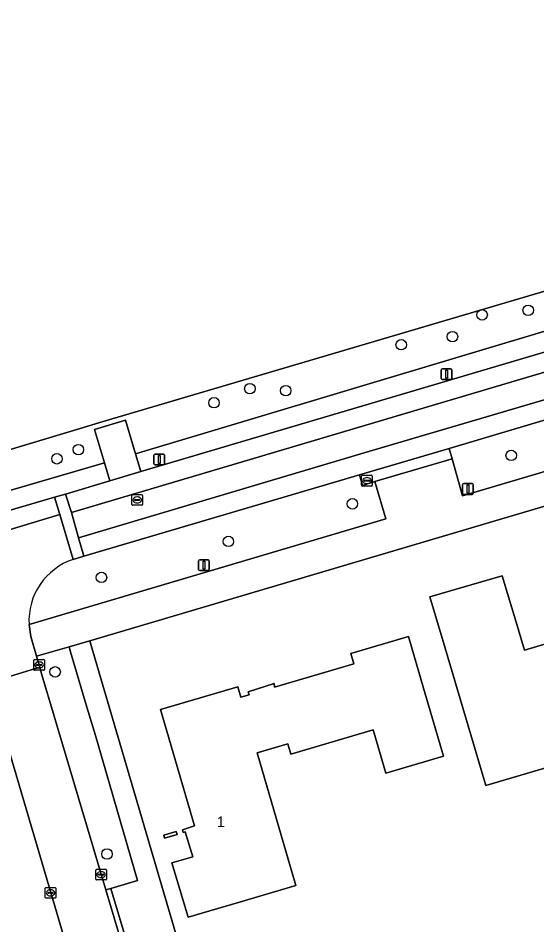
# Model space of a CAD drawing. Extents: x 162417 to 163722, y 384268 to 385417.
# Drawn here: x 163303.2 to 163351.6, y 384656 to 384740.4 of the extents above; entities that cross this region are included whole.
import ezdxf

# ---------------------------------------------------------------- set-up
doc = ezdxf.new("R2010")
doc.units = 0
for name, color, linetype in [('IMGEO_Berm_groen', 7, 'Continuous'), ('IMGEO_Boom', 7, 'Continuous'), ('IMGEO_Erf', 7, 'Continuous'), ('IMGEO_Groenvoorziening', 7, 'Continuous'), ('IMGEO_Hek', 7, 'Continuous'), ('IMGEO_Kolk', 7, 'Continuous'), ('IMGEO_Lichtmast', 7, 'Continuous'), ('IMGEO_Pand', 7, 'Continuous'), ('IMGEO_Pand_nummerreeks', 7, 'Continuous'), ('IMGEO_Rijbaan_lokaal_gesloten', 7, 'Continuous'), ('IMGEO_Rijbaan_lokaal_open', 7, 'Continuous'), ('IMGEO_Rioolput', 7, 'Continuous'), ('IMGEO_Voetpad_open', 7, 'Continuous')]:
    doc.layers.add(name, color=color, linetype=linetype)

msp = doc.modelspace()

# ---------------------------------------------------------------- linework, layer by layer
at = {"layer": 'IMGEO_Berm_groen'}
msp.add_lwpolyline([(163310.423, 384673.599), (163309.634, 384676.252), (163308.098, 384681.397), (163307.99, 384681.867), (163304.927, 384681.002), (163305.248, 384679.964), (163305.445, 384679.26), (163306.588, 384675.415), (163311.404, 384659.211), (163311.865, 384659.348), (163314.36, 384660.087)], close=True, dxfattribs=at)
at = {"layer": 'IMGEO_Boom'}
for centre in [(163350.764, 384713.205), (163346.474, 384712.775), (163343.706, 384710.75), (163338.932, 384709.998), (163324.825, 384705.903), (163328.166, 384705.722), (163321.48, 384704.594), (163308.84, 384700.227), (163349.182, 384699.69), (163306.838, 384699.373), (163334.381, 384695.178), (163322.822, 384691.68), (163310.99, 384688.327), (163306.669, 384679.527), (163311.506, 384662.56)]:
    msp.add_circle(centre, 0.489, dxfattribs=at)
at = {"layer": 'IMGEO_Erf'}
for points in [[(163175.984, 384894.871), (163189.317, 384805.604), (163189.37, 384805.252), (163225.47, 384820.661), (163226.246, 384820.995), (163226.612, 384820.203), (163229.945, 384812.987), (163225.751, 384811.048), (163227.566, 384807.013), (163229.658, 384807.895), (163230.655, 384805.678), (163228.563, 384804.796), (163224.144, 384802.92), (163192.437, 384789.411), (163200.664, 384750), (163215.633, 384678.291), (163252.312, 384685.775), (163256.147, 384686.557), (163258.646, 384687.067), (163309.002, 384702.202), (163311.14, 384702.845), (163432.284, 384738.586)], [(163439.207, 384659.583), (163443.713, 384668.387), (163445.245, 384671.173), (163447.549, 384675.363), (163448.047, 384676.269), (163448.203, 384676.553), (163447.906, 384676.713), (163460.651, 384701.67), (163461.429, 384701.275), (163462.377, 384703.14), (163461.604, 384703.558), (163465.046, 384710.362), (163457.241, 384724.223), (163456.356, 384725.796), (163426.302, 384716.894), (163404.174, 384710.339), (163359.949, 384697.239), (163309.903, 384682.414), (163310.09, 384681.76), (163333.508, 384602.071)], [(163310.764, 384635.802), (163312.926, 384636.415), (163300.634, 384677.935), (163300.352, 384678.47), (163299.946, 384679.602), (163217.164, 384655.09), (163211.589, 384653.439), (163162.154, 384638.801), (163163.733, 384633.465), (163163.883, 384632.961), (163162.442, 384632.589), (163160.726, 384632.111), (163162.281, 384626.769), (163162.11, 384626.271), (163182.33, 384558.292), (163182.739, 384554.615), (163182.929, 384552.906)]]:
    msp.add_lwpolyline(points, dxfattribs=at)
for points in [[(163363.589, 384671.02), (163357.808, 384669.308), (163356.639, 384673.259), (163353.178, 384672.234), (163353.565, 384670.93), (163346.815, 384668.931), (163343.025, 384681.732), (163341.605, 384686.526), (163348.348, 384688.485), (163349.733, 384683.848), (163350.422, 384681.542), (163353.862, 384682.572), (163353.177, 384684.891), (163353.045, 384685.336), (163358.845, 384687.038), (163360.265, 384682.244)], [(163341.017, 384678.019), (163342.88, 384671.666), (163337.507, 384670.091), (163336.326, 384674.122), (163328.65, 384671.872), (163328.369, 384672.832), (163325.491, 384671.988), (163329.116, 384659.629), (163323.865, 384658.089), (163319.067, 384656.682), (163317.564, 384661.73), (163319.491, 384662.304), (163318.804, 384664.614), (163318.613, 384664.557), (163318.553, 384664.813), (163319.674, 384665.19), (163316.483, 384676.015), (163323.701, 384678.122), (163323.982, 384677.163), (163324.76, 384677.39), (163324.676, 384677.678), (163327.076, 384678.428), (163327.112, 384678.101), (163334.498, 384680.283), (163334.242, 384681.242), (163339.61, 384682.816)], [(163316.881, 384664.023), (163316.81, 384664.316), (163317.961, 384664.654), (163318.048, 384664.37)]]:
    msp.add_lwpolyline(points, close=True, dxfattribs=at)
at = {"layer": 'IMGEO_Groenvoorziening'}
for points in [[(163434.845, 384735.97), (163434.107, 384738.766), (163432.394, 384738.238), (163432.284, 384738.586), (163311.14, 384702.845), (163309.002, 384702.202), (163258.646, 384687.067), (163256.147, 384686.557), (163256.857, 384683.119), (163311.275, 384698.988), (163310.335, 384702.113), (163313.232, 384702.984), (163314.169, 384699.824)], [(163378.093, 384716.936), (163379.085, 384717.235), (163384.338, 384718.783), (163385.387, 384719.108), (163412.606, 384727.101), (163435.394, 384733.889), (163434.845, 384735.97), (163314.169, 384699.824), (163314.653, 384698.19)], [(163375.527, 384705.045), (163374.472, 384708.486), (163373.407, 384708.185), (163373.123, 384709.18), (163343.412, 384700.333), (163343.683, 384699.355), (163344.653, 384695.917)], [(163289.436, 384690.763), (163290.424, 384691.053), (163306.618, 384695.814), (163307.647, 384696.083), (163311.775, 384697.325), (163311.275, 384698.988), (163256.857, 384683.119), (163257.233, 384681.296)]]:
    msp.add_lwpolyline(points, close=True, dxfattribs=at)
for points in [[(163337.499, 384693.791), (163336.478, 384697.246), (163335.325, 384696.897), (163335.047, 384697.894), (163309.345, 384690.294), (163308.357, 384690.004)], [(163304.239, 384683.939), (163337.499, 384693.791)]]:
    msp.add_lwpolyline(points, dxfattribs=at)
msp.add_arc((163310.267, 384684.277), 6.037, 108.44151, 183.20723, dxfattribs=at)
at = {"layer": 'IMGEO_Hek'}
msp.add_lwpolyline([(163309.002, 384702.202), (163311.14, 384702.845)], dxfattribs=at)
at = {"layer": 'IMGEO_Kolk'}
for p, q in [((163335.233, 384696.91), (163335.233, 384697.762)), ((163335.308, 384697.836), (163336.16, 384697.836)), ((163336.234, 384697.762), (163336.234, 384696.91)), ((163336.16, 384696.836), (163335.308, 384696.836)), ((163335.492, 384697.33), (163335.492, 384697.342)), ((163335.93, 384697.293), (163335.532, 384697.293)), ((163335.535, 384697.379), (163335.933, 384697.379)), ((163335.744, 384697.056), (163335.719, 384697.056)), ((163335.721, 384697.616), (163335.746, 384697.616)), ((163335.976, 384697.342), (163335.976, 384697.33)), ((163304.675, 384679.749), (163304.675, 384680.601)), ((163304.75, 384680.675), (163305.602, 384680.675)), ((163304.934, 384680.169), (163304.934, 384680.181)), ((163305.372, 384680.132), (163304.974, 384680.132)), ((163304.977, 384680.218), (163305.375, 384680.218)), ((163305.163, 384680.455), (163305.188, 384680.455)), ((163305.418, 384680.181), (163305.418, 384680.169)), ((163305.676, 384680.601), (163305.676, 384679.749)), ((163305.602, 384679.675), (163304.75, 384679.675)), ((163305.186, 384679.895), (163305.161, 384679.895)), ((163310.459, 384660.215), (163310.459, 384661.067)), ((163310.534, 384661.141), (163311.386, 384661.141)), ((163310.718, 384660.635), (163310.718, 384660.647)), ((163311.156, 384660.598), (163310.758, 384660.598)), ((163310.761, 384660.684), (163311.159, 384660.684)), ((163310.947, 384660.921), (163310.972, 384660.921)), ((163311.202, 384660.647), (163311.202, 384660.635)), ((163311.46, 384661.067), (163311.46, 384660.215)), ((163311.386, 384660.141), (163310.534, 384660.141)), ((163310.97, 384660.361), (163310.945, 384660.361)), ((163305.74, 384658.517), (163305.74, 384659.369)), ((163305.815, 384659.443), (163306.667, 384659.443)), ((163305.999, 384658.937), (163305.999, 384658.949)), ((163306.437, 384658.9), (163306.039, 384658.9)), ((163306.042, 384658.986), (163306.44, 384658.986)), ((163306.228, 384659.223), (163306.253, 384659.223)), ((163306.483, 384658.949), (163306.483, 384658.937)), ((163306.741, 384659.369), (163306.741, 384658.517)), ((163306.667, 384658.443), (163305.815, 384658.443)), ((163306.251, 384658.663), (163306.226, 384658.663))]:
    msp.add_line(p, q, dxfattribs=at)
for points in [[(163335.233, 384696.91), (163335.233, 384697.762)], [(163335.308, 384697.836), (163336.16, 384697.836)], [(163336.234, 384697.762), (163336.234, 384696.91)], [(163336.16, 384696.836), (163335.308, 384696.836)], [(163304.675, 384679.749), (163304.675, 384680.601)], [(163304.75, 384680.675), (163305.602, 384680.675)], [(163305.676, 384680.601), (163305.676, 384679.749)], [(163305.602, 384679.675), (163304.75, 384679.675)], [(163310.459, 384660.215), (163310.459, 384661.067)], [(163310.534, 384661.141), (163311.386, 384661.141)], [(163311.46, 384661.067), (163311.46, 384660.215)], [(163311.386, 384660.141), (163310.534, 384660.141)], [(163305.74, 384658.517), (163305.74, 384659.369)], [(163305.815, 384659.443), (163306.667, 384659.443)], [(163306.741, 384659.369), (163306.741, 384658.517)], [(163306.667, 384658.443), (163305.815, 384658.443)]]:
    msp.add_lwpolyline(points, dxfattribs=at)
for centre, radius, start, end in [((163335.31, 384697.76), 0.0765, 91.55205, 178.44795), ((163335.31, 384697.76), 0.0765, 91.55205, 178.44795), ((163336.158, 384697.76), 0.0765, 1.55205, 88.44795), ((163336.158, 384697.76), 0.0765, 1.55205, 88.44795), ((163335.31, 384696.912), 0.0765, 181.55205, 268.44795), ((163335.31, 384696.912), 0.0765, 181.55205, 268.44795), ((163335.532, 384697.339), 0.0403, 85.87752, 175.75265), ((163335.529, 384697.329), 0.0366, 178.93798, 274.71019), ((163335.933, 384697.336), 0.043, 264.86636, 352.45326), ((163335.937, 384697.341), 0.0386, 1.73085, 96.63898), ((163336.158, 384696.912), 0.0765, 271.55205, 358.44795), ((163336.158, 384696.912), 0.0765, 271.55205, 358.44795), ((163304.752, 384680.599), 0.0765, 91.55205, 178.44795), ((163304.752, 384680.599), 0.0765, 91.55205, 178.44795), ((163304.974, 384680.178), 0.0403, 85.87752, 175.75265), ((163304.971, 384680.168), 0.0366, 178.93798, 274.71019), ((163305.375, 384680.175), 0.043, 264.86636, 352.45326), ((163305.379, 384680.18), 0.0386, 1.73085, 96.63898), ((163305.6, 384680.599), 0.0765, 1.55205, 88.44795), ((163305.6, 384680.599), 0.0765, 1.55205, 88.44795), ((163304.752, 384679.751), 0.0765, 181.55205, 268.44795), ((163304.752, 384679.751), 0.0765, 181.55205, 268.44795), ((163305.6, 384679.751), 0.0765, 271.55205, 358.44795), ((163305.6, 384679.751), 0.0765, 271.55205, 358.44795), ((163310.536, 384661.065), 0.0765, 91.55205, 178.44795), ((163310.536, 384661.065), 0.0765, 91.55205, 178.44795), ((163310.758, 384660.644), 0.0403, 85.87752, 175.75265), ((163310.755, 384660.634), 0.0366, 178.93798, 274.71019), ((163311.159, 384660.641), 0.043, 264.86636, 352.45326), ((163311.163, 384660.646), 0.0386, 1.73085, 96.63898), ((163311.384, 384661.065), 0.0765, 1.55205, 88.44795), ((163311.384, 384661.065), 0.0765, 1.55205, 88.44795), ((163310.536, 384660.217), 0.0765, 181.55205, 268.44795), ((163310.536, 384660.217), 0.0765, 181.55205, 268.44795), ((163311.384, 384660.217), 0.0765, 271.55205, 358.44795), ((163311.384, 384660.217), 0.0765, 271.55205, 358.44795), ((163305.817, 384659.367), 0.0765, 91.55205, 178.44795), ((163305.817, 384659.367), 0.0765, 91.55205, 178.44795), ((163306.039, 384658.946), 0.0403, 85.87752, 175.75265), ((163306.036, 384658.936), 0.0366, 178.93798, 274.71019), ((163306.44, 384658.943), 0.043, 264.86636, 352.45326), ((163306.444, 384658.948), 0.0386, 1.73085, 96.63898), ((163306.665, 384659.367), 0.0765, 1.55205, 88.44795), ((163306.665, 384659.367), 0.0765, 1.55205, 88.44795), ((163305.817, 384658.519), 0.0765, 181.55205, 268.44795), ((163305.817, 384658.519), 0.0765, 181.55205, 268.44795), ((163306.665, 384658.519), 0.0765, 271.55205, 358.44795), ((163306.665, 384658.519), 0.0765, 271.55205, 358.44795)]:
    msp.add_arc(centre, radius, start, end, dxfattribs=at)
for centre, major_axis, ratio, start_param, end_param in [((163335.72, 384697.336), (-0.387, 0.002), 0.722429, 4.712389, 7.853982), ((163335.745, 384697.336), (-0.39, 0.002), 0.717154, 1.570796, 4.712389), ((163305.162, 384680.175), (-0.387, 0.002), 0.722429, 4.712389, 7.853982), ((163305.187, 384680.175), (-0.39, 0.002), 0.717154, 1.570796, 4.712389), ((163310.946, 384660.641), (-0.387, 0.002), 0.722429, 4.712389, 7.853982), ((163310.971, 384660.641), (-0.39, 0.002), 0.717154, 1.570796, 4.712389), ((163306.227, 384658.943), (-0.387, 0.002), 0.722429, 4.712389, 7.853982), ((163306.252, 384658.943), (-0.39, 0.002), 0.717154, 1.570796, 4.712389)]:
    msp.add_ellipse(centre, major_axis=major_axis, ratio=ratio, start_param=start_param, end_param=end_param, dxfattribs=at)
at = {"layer": 'IMGEO_Lichtmast'}
for p, q in [((163342.664, 384706.864), (163342.664, 384707.664)), ((163342.664, 384707.664), (163342.664, 384706.864)), ((163342.764, 384707.764), (163343.554, 384707.764)), ((163343.554, 384707.764), (163342.764, 384707.764)), ((163343.654, 384707.664), (163343.654, 384706.864)), ((163343.654, 384706.864), (163343.654, 384707.664)), ((163343.554, 384706.764), (163342.764, 384706.764)), ((163342.764, 384706.764), (163343.554, 384706.764)), ((163315.882, 384698.906), (163315.882, 384699.706)), ((163315.882, 384699.706), (163315.882, 384698.906)), ((163315.982, 384699.806), (163316.772, 384699.806)), ((163316.772, 384699.806), (163315.982, 384699.806)), ((163316.872, 384699.706), (163316.872, 384698.906)), ((163316.872, 384698.906), (163316.872, 384699.706)), ((163316.772, 384698.806), (163315.982, 384698.806)), ((163315.982, 384698.806), (163316.772, 384698.806)), ((163344.657, 384696.161), (163344.657, 384696.961)), ((163344.657, 384696.961), (163344.657, 384696.161)), ((163344.757, 384697.061), (163345.547, 384697.061)), ((163345.547, 384697.061), (163344.757, 384697.061)), ((163345.647, 384696.961), (163345.647, 384696.161)), ((163345.647, 384696.161), (163345.647, 384696.961)), ((163345.547, 384696.061), (163344.757, 384696.061)), ((163344.757, 384696.061), (163345.547, 384696.061)), ((163320.047, 384689.071), (163320.047, 384689.871)), ((163320.047, 384689.871), (163320.047, 384689.071)), ((163320.147, 384689.971), (163320.937, 384689.971)), ((163320.937, 384689.971), (163320.147, 384689.971)), ((163321.037, 384689.871), (163321.037, 384689.071)), ((163321.037, 384689.071), (163321.037, 384689.871)), ((163320.937, 384688.971), (163320.147, 384688.971)), ((163320.147, 384688.971), (163320.937, 384688.971))]:
    msp.add_line(p, q, dxfattribs=at)
for points in [[(163343.084, 384707.639), (163343.234, 384707.639), (163343.234, 384706.889), (163343.084, 384706.889), (163343.084, 384707.639)], [(163316.302, 384699.681), (163316.452, 384699.681), (163316.452, 384698.931), (163316.302, 384698.931), (163316.302, 384699.681)], [(163345.077, 384696.936), (163345.227, 384696.936), (163345.227, 384696.186), (163345.077, 384696.186), (163345.077, 384696.936)], [(163320.467, 384689.846), (163320.617, 384689.846), (163320.617, 384689.096), (163320.467, 384689.096), (163320.467, 384689.846)]]:
    msp.add_lwpolyline(points, dxfattribs=at)
for centre, start, end in [((163342.764, 384707.664), 90, 180), ((163342.764, 384707.664), 90, 180), ((163343.554, 384707.664), 0, 90), ((163343.554, 384707.664), 360, 90), ((163342.764, 384706.864), 180, 270), ((163342.764, 384706.864), 180, 270), ((163343.554, 384706.864), 270, 0), ((163343.554, 384706.864), 270, 0), ((163315.982, 384699.706), 90, 180), ((163315.982, 384699.706), 90, 180), ((163316.772, 384699.706), 0, 90), ((163316.772, 384699.706), 360, 90), ((163315.982, 384698.906), 180, 270), ((163315.982, 384698.906), 180, 270), ((163316.772, 384698.906), 270, 0), ((163316.772, 384698.906), 270, 0), ((163344.757, 384696.961), 90, 180), ((163344.757, 384696.961), 90, 180), ((163345.547, 384696.961), 0, 90), ((163345.547, 384696.961), 360, 90), ((163344.757, 384696.161), 180, 270), ((163344.757, 384696.161), 180, 270), ((163345.547, 384696.161), 270, 0), ((163345.547, 384696.161), 270, 0), ((163320.147, 384689.871), 90, 180), ((163320.147, 384689.871), 90, 180), ((163320.937, 384689.871), 0, 90), ((163320.937, 384689.871), 360, 90), ((163320.147, 384689.071), 180, 270), ((163320.147, 384689.071), 180, 270), ((163320.937, 384689.071), 270, 0), ((163320.937, 384689.071), 270, 0)]:
    msp.add_arc(centre, 0.1, start, end, dxfattribs=at)
at = {"layer": 'IMGEO_Pand'}
for points in [[(163346.815, 384668.931), (163353.565, 384670.93), (163353.178, 384672.234), (163356.639, 384673.259), (163357.808, 384669.308), (163363.589, 384671.02), (163360.265, 384682.244), (163358.845, 384687.038), (163353.045, 384685.336), (163353.177, 384684.891), (163353.862, 384682.572), (163350.422, 384681.542), (163349.733, 384683.848), (163348.348, 384688.485), (163341.605, 384686.526), (163343.025, 384681.732)], [(163339.61, 384682.816), (163334.242, 384681.242), (163334.498, 384680.283), (163327.112, 384678.101), (163327.076, 384678.428), (163324.676, 384677.678), (163324.76, 384677.39), (163323.982, 384677.163), (163323.701, 384678.122), (163316.483, 384676.015), (163319.674, 384665.19), (163318.553, 384664.813), (163318.613, 384664.557), (163318.804, 384664.614), (163319.491, 384662.304), (163317.564, 384661.73), (163319.067, 384656.682), (163323.865, 384658.089), (163329.116, 384659.629), (163325.491, 384671.988), (163328.369, 384672.832), (163328.65, 384671.872), (163336.326, 384674.122), (163337.507, 384670.091), (163342.88, 384671.666), (163341.017, 384678.019)], [(163316.81, 384664.316), (163316.881, 384664.023), (163318.048, 384664.37), (163317.961, 384664.654)]]:
    msp.add_lwpolyline(points, close=True, dxfattribs=at)
at = {"layer": 'IMGEO_Rijbaan_lokaal_gesloten'}
for points in [[(163314.653, 384698.19), (163311.775, 384697.325), (163307.647, 384696.083), (163308.184, 384694.376), (163378.569, 384715.229), (163378.093, 384716.936)], [(163379.769, 384711.14), (163379.278, 384712.828), (163335.473, 384699.928), (163308.845, 384692.001), (163309.345, 384690.294), (163335.047, 384697.894), (163343.412, 384700.333), (163373.123, 384709.18), (163377.923, 384710.618)], [(163290.424, 384691.053), (163290.945, 384689.301), (163307.122, 384694.182), (163306.618, 384695.814)]]:
    msp.add_lwpolyline(points, close=True, dxfattribs=at)
at = {"layer": 'IMGEO_Rijbaan_lokaal_open'}
for points in [[(163379.278, 384712.828), (163378.569, 384715.229), (163308.184, 384694.376), (163308.845, 384692.001), (163335.473, 384699.928)], [(163308.357, 384690.004), (163309.345, 384690.294), (163308.845, 384692.001), (163308.184, 384694.376), (163307.647, 384696.083), (163306.618, 384695.814), (163307.122, 384694.182)]]:
    msp.add_lwpolyline(points, close=True, dxfattribs=at)
for points in [[(163308.357, 384690.004), (163307.122, 384694.182), (163290.945, 384689.301), (163292.104, 384685.298)], [(163298.709, 384682.365), (163299.946, 384679.602), (163300.352, 384678.47), (163305.248, 384679.964), (163304.927, 384681.002), (163304.395, 384682.827), (163304.239, 384683.939)], [(163322.986, 384620.355), (163322.7, 384621.313), (163321.795, 384624.338), (163321.537, 384625.199), (163317.662, 384638.152), (163313.725, 384651.399), (163311.404, 384659.211), (163306.588, 384675.415), (163305.445, 384679.26), (163305.248, 384679.964), (163300.352, 384678.47), (163300.634, 384677.935), (163312.926, 384636.415), (163317.237, 384621.888), (163323.475, 384600.863), (163323.936, 384598.792), (163323.763, 384596.699)]]:
    msp.add_lwpolyline(points, dxfattribs=at)
msp.add_arc((163310.267, 384684.277), 6.037, 108.44151, 183.20723, dxfattribs=at)
at = {"layer": 'IMGEO_Rioolput'}
for p, q in [((163313.82, 384695.117), (163313.82, 384695.969)), ((163313.895, 384696.043), (163314.747, 384696.043)), ((163314.821, 384695.969), (163314.821, 384695.117)), ((163314.079, 384695.537), (163314.079, 384695.549)), ((163314.517, 384695.5), (163314.119, 384695.5)), ((163314.122, 384695.586), (163314.52, 384695.586)), ((163314.331, 384695.263), (163314.306, 384695.263)), ((163314.308, 384695.823), (163314.333, 384695.823)), ((163314.563, 384695.549), (163314.563, 384695.537)), ((163314.747, 384695.043), (163313.895, 384695.043))]:
    msp.add_line(p, q, dxfattribs=at)
for points in [[(163313.82, 384695.117), (163313.82, 384695.969)], [(163313.895, 384696.043), (163314.747, 384696.043)], [(163314.821, 384695.969), (163314.821, 384695.117)], [(163314.747, 384695.043), (163313.895, 384695.043)]]:
    msp.add_lwpolyline(points, dxfattribs=at)
for centre, radius, start, end in [((163313.897, 384695.967), 0.0765, 91.55205, 178.44795), ((163313.897, 384695.967), 0.0765, 91.55205, 178.44795), ((163314.745, 384695.967), 0.0765, 1.55205, 88.44795), ((163314.745, 384695.967), 0.0765, 1.55205, 88.44795), ((163313.897, 384695.119), 0.0765, 181.55205, 268.44795), ((163313.897, 384695.119), 0.0765, 181.55205, 268.44795), ((163314.119, 384695.546), 0.0403, 85.87752, 175.75265), ((163314.116, 384695.536), 0.0366, 178.93798, 274.71019), ((163314.52, 384695.543), 0.043, 264.86636, 352.45326), ((163314.524, 384695.548), 0.0386, 1.73085, 96.63898), ((163314.745, 384695.119), 0.0765, 271.55205, 358.44795), ((163314.745, 384695.119), 0.0765, 271.55205, 358.44795)]:
    msp.add_arc(centre, radius, start, end, dxfattribs=at)
for centre, major_axis, ratio, start_param, end_param in [((163314.307, 384695.543), (-0.387, 0.002), 0.722429, 4.712389, 7.853982), ((163314.332, 384695.543), (-0.39, 0.002), 0.717154, 1.570796, 4.712389)]:
    msp.add_ellipse(centre, major_axis=major_axis, ratio=ratio, start_param=start_param, end_param=end_param, dxfattribs=at)
at = {"layer": 'IMGEO_Voetpad_open'}
msp.add_lwpolyline([(163375.527, 384705.045), (163344.653, 384695.917), (163343.683, 384699.355), (163336.478, 384697.246), (163337.499, 384693.791), (163304.239, 384683.939), (163304.395, 384682.827), (163304.927, 384681.002), (163307.99, 384681.867), (163309.903, 384682.414), (163359.949, 384697.239)], dxfattribs=at)
for points in [[(163313.232, 384702.984), (163310.335, 384702.113), (163311.275, 384698.988), (163311.775, 384697.325), (163314.653, 384698.19), (163314.169, 384699.824)], [(163343.683, 384699.355), (163343.412, 384700.333), (163335.047, 384697.894), (163335.325, 384696.897), (163336.478, 384697.246)], [(163310.09, 384681.76), (163309.903, 384682.414), (163307.99, 384681.867), (163308.098, 384681.397), (163309.634, 384676.252), (163310.423, 384673.599), (163314.36, 384660.087), (163311.865, 384659.348), (163314.204, 384651.541), (163316.675, 384652.273), (163319.815, 384641.564), (163320.535, 384638.911), (163324.332, 384626.062), (163321.537, 384625.199), (163321.795, 384624.338), (163324.587, 384625.199), (163325.485, 384622.16), (163325.769, 384621.2), (163331.704, 384601.119), (163333.508, 384602.071)], [(163314.204, 384651.541), (163311.865, 384659.348), (163311.404, 384659.211), (163313.725, 384651.399)]]:
    msp.add_lwpolyline(points, close=True, dxfattribs=at)

# ---------------------------------------------------------------- texts
at = {"layer": 'IMGEO_Pand_nummerreeks'}
msp.add_text('1', height=1, dxfattribs=at).set_placement((163321.749, 384665.062))

doc.saveas('drawing.dxf')
